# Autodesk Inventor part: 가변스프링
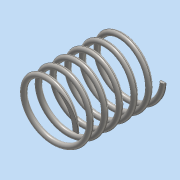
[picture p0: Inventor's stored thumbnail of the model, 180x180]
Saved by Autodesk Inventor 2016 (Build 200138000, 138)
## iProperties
Created: 2018-11
Part Number: 가변스프링
Material: 스테인레스 스틸
Document SubType Name: Modeling
Designer: user
Density: 8 g/cm^3
Appearance: 반연마
Mass: 84.1985 g
Surface Area: 106.475 cm^2
Volume: 10.5248 cm^3
Author: user
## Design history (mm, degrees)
sketch "스케치1"
  geometry: L1 (0, 0)-(22.5, 0); L2 (22.5, 0)-(22.5, 67.25); L3 (22.5, 67.25)-(0, 67.25); L4 (0, 67.25)-(0, 0); C1 r 2 at (22.5, 0)
  constraints: 8 end point, 2 parallel, 1 centre point, 1 coincident, 1 horizontal, 1 perpendicular
  dimensions: "d0" = 4 diameter of C1; "d1" = 45 diameter of L2 L4; "d2" = 67.25 distance of L3.end L1.start (derived)
feature "코일1" sketch "스케치1" pitch "d3" = 10; turns "d5" = 6; dims "d4" = 67.25 (= d2), "d6" = 0, angle "d7" = 90 deg, angle "d8" = 90 deg, "d9" = 0, "d10" = 0
sketch "스케치2"
  geometry: L1 (-49.505, 0)-(49.505, 0); L2 (49.505, 0)-(49.505, 67.25); L3 (49.505, 67.25)-(-49.505, 67.25); L4 (-49.505, 67.25)-(-49.505, 0); 2 further points
  constraints: 8 end point, 2 parallel, 1 coincident, 1 horizontal, 1 midpoint, 1 perpendicular
  dimensions: "d11" = 99.00983 distance between parallel lines of L2 L4; "d12" = 67.25 distance between parallel lines of L1 L3 (= d2)
extrude "돌출1" sketch "스케치2" stored distance "d13" = 100; taper "d14" = 0 deg
node "솔리드1"
